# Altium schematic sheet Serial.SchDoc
size B
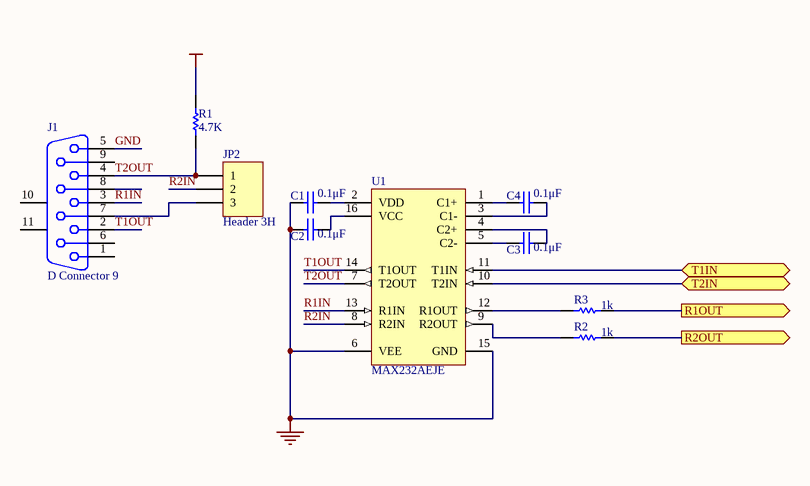
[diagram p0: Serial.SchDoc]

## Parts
C1  0.1μF  [RAD-0.3]
C2  0.1μF  [RAD-0.3]
C3  0.1μF  [RAD-0.3]
C4  0.1μF  [RAD-0.3]
J1  D Connector 9  [DSUB1.385-2H9]
JP2  Header 3H  [HDR1X3H]
R1  4.7K  [AXIAL-0.3]
R2  1k  [AXIAL-0.3]
R3  1k  [AXIAL-0.3]
U1  MAX232AEJE  [DIP-16/D21.7]

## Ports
R1OUT (out), R2OUT (out), T1IN (bidir), T2IN

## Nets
GND: C1.1 C2.1 J1.5 U1.6(VEE) U1.15(GND)
VCC: R1.2
R1IN: J1.3 U1.13(R1IN)
R1OUT: R3.1 ; port R1OUT
R2IN: JP2.2 U1.8(R2IN)
R2OUT: R2.1 ; port R2OUT
T1IN: U1.11(T1IN) ; port T1IN
T1OUT: J1.2 U1.14(T1OUT)
T2IN: U1.10(T2IN) ; port T2IN
T2OUT: J1.4 JP2.1 R1.1 U1.7(T2OUT)
NetC1_2: C1.2 U1.2(VDD)
NetC2_2: C2.2 U1.16(VCC)
NetC3_1: C3.1 U1.5(C2-)
NetC3_2: C3.2 U1.4(C2+)
NetC4_1: C4.1 U1.1(C1+)
NetC4_2: C4.2 U1.3(C1-)
NetJ1_7: J1.7 JP2.3
NetR2_2: R2.2 U1.9(R2OUT)
NetR3_2: R3.2 U1.12(R1OUT)

Not connected (* = marked no-connect by the designer): J1 1 6 8 9 10(MH1) 11(MH2)

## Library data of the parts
C1-C4 = Cap: Capacitor; Manufacturer: Generic Components; Class I: Passive
J1 = D Connector 9: Receptacle Assembly, 9 Position, Right Angle; Manufacturer: Generic Components; Package Information: Latest Revision: O; Positions: 9
JP2 = Header 3H: Header, 3-Pin,  Right Angle; Manufacturer: Generic Components; Class I: Connector
R1 = Res1: Resistor; Manufacturer: Generic Components; Class I: Passive; Value: 1K
R2 R3 = Res1: Resistor; Manufacturer: Generic Components; Class I: Passive
U1 = MAX232AEJE: +5V Powered, Multi-Channel RS-232 Driver/Receiver; Manufacturer: Maxim; Class I: Communication; Class II: Transceiver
